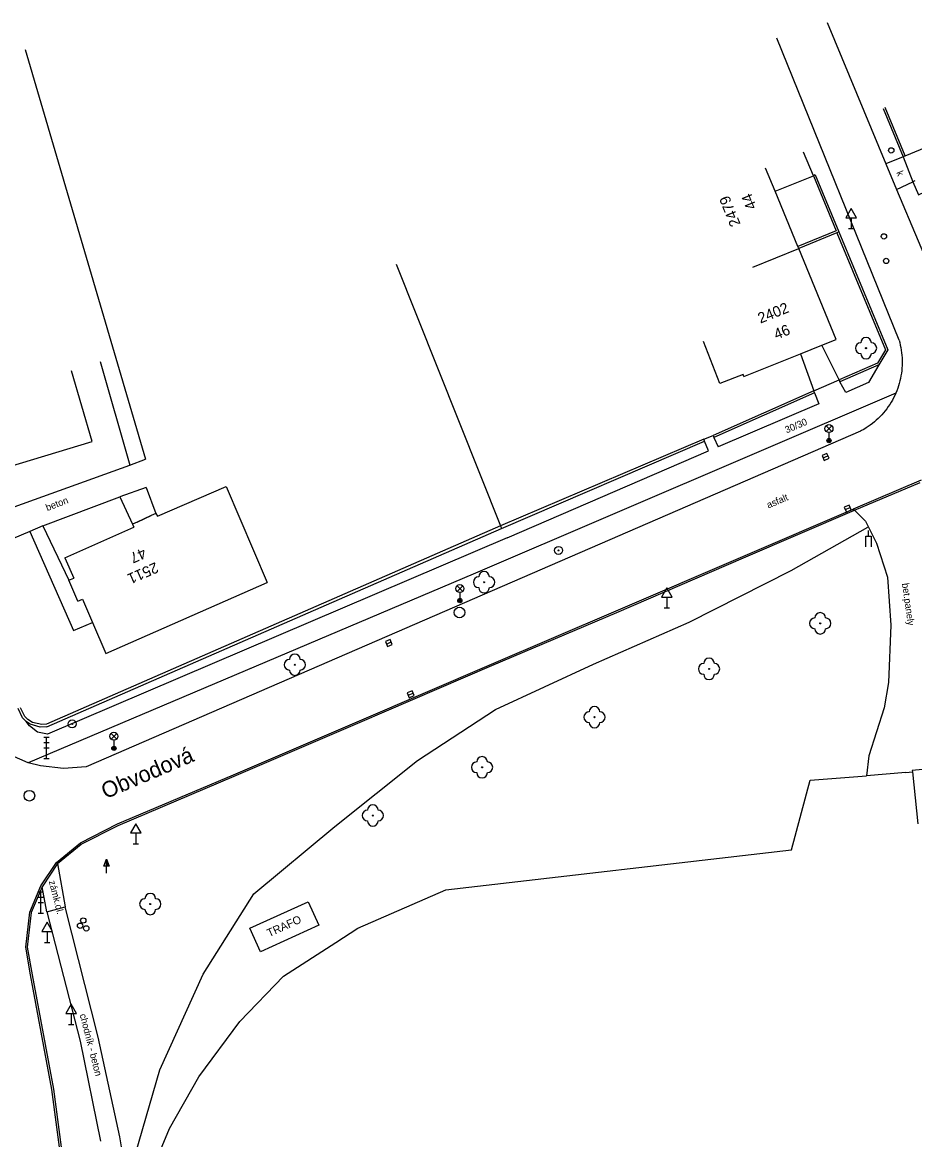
# Model space of a CAD drawing. Extents: x -539694 to -539148, y -1156467 to -1155920.
# Drawn here: x -539640.2 to -539556.6, y -1156122.8 to -1156018.1 of the extents above; entities that cross this region are included whole.
import ezdxf

# ---------------------------------------------------------------- set-up
doc = ezdxf.new("R2010")
doc.units = 0
for name, color, linetype in [('Vrstva 10', 7, 'Continuous'), ('Vrstva 11', 7, 'Continuous'), ('Vrstva 21', 7, 'Continuous'), ('Vrstva 22', 7, 'Continuous'), ('Vrstva 23', 7, 'Continuous'), ('Vrstva 25', 7, 'Continuous'), ('Vrstva 27', 7, 'Continuous'), ('Vrstva 28', 7, 'Continuous'), ('Vrstva 33', 7, 'Continuous'), ('Vrstva 34', 7, 'Continuous'), ('Vrstva 38', 7, 'Continuous'), ('Vrstva 40', 7, 'Continuous'), ('Vrstva 41', 7, 'Continuous'), ('Vrstva 46', 7, 'Continuous'), ('Vrstva 47', 7, 'Continuous'), ('Vrstva 49', 7, 'Continuous'), ('Vrstva 5', 7, 'Continuous'), ('Vrstva 6', 7, 'Continuous'), ('Vrstva 7', 7, 'Continuous'), ('Vrstva 8', 7, 'Continuous')]:
    doc.layers.add(name, color=color, linetype=linetype)

msp = doc.modelspace()

# ---------------------------------------------------------------- linework, layer by layer
at = {"layer": 'Vrstva 10'}
for p, q in [((-539564.79, -1156018.12), (-539559.31, -1156031.39)), ((-539558.07, -1156047.89), (-539569.52, -1156019.6)), ((-539559.31, -1156031.39), (-539558.31, -1156033.77)), ((-539558.31, -1156033.77), (-539553.97, -1156044.1)), ((-539561.68, -1156056.43), (-539634.18, -1156087.87)), ((-539561.575, -1156056.374), (-539561.68, -1156056.43))]:
    msp.add_line(p, q, dxfattribs=at)
for points in [[(-539558.07, -1156047.89), (-539558.006, -1156048.123), (-539557.949, -1156048.359), (-539557.9, -1156048.596), (-539557.859, -1156048.834), (-539557.826, -1156049.074), (-539557.801, -1156049.314), (-539557.784, -1156049.556), (-539557.775, -1156049.798), (-539557.773, -1156050.04), (-539557.78, -1156050.281), (-539557.795, -1156050.523), (-539557.818, -1156050.764), (-539557.849, -1156051.004), (-539557.887, -1156051.243), (-539557.934, -1156051.48), (-539557.988, -1156051.716), (-539558.05, -1156051.95), (-539558.12, -1156052.182), (-539558.197, -1156052.411), (-539558.282, -1156052.637), (-539558.37, -1156052.85), (-539558.475, -1156053.082), (-539558.582, -1156053.299), (-539558.696, -1156053.512), (-539558.817, -1156053.722), (-539558.945, -1156053.927), (-539559.079, -1156054.128), (-539559.221, -1156054.324), (-539559.368, -1156054.516), (-539559.522, -1156054.703), (-539559.682, -1156054.884), (-539559.848, -1156055.061), (-539560.02, -1156055.231), (-539560.197, -1156055.396), (-539560.379, -1156055.555), (-539560.567, -1156055.708), (-539560.76, -1156055.854), (-539560.957, -1156055.994), (-539561.159, -1156056.127), (-539561.365, -1156056.254), (-539561.575, -1156056.374)], [(-539639.62, -1156087.49), (-539641.674, -1156086.595), (-539643.293, -1156085.512), (-539643.537, -1156085.349), (-539645.149, -1156083.793), (-539646.11, -1156082.53)], [(-539634.18, -1156087.87), (-539636.324, -1156088.031), (-539638.461, -1156087.793), (-539639.62, -1156087.49)]]:
    msp.add_lwpolyline(points, dxfattribs=at)
at = {"layer": 'Vrstva 11'}
for p, q in [((-539639.894, -1156020.661), (-539628.648, -1156059.042)), ((-539557.485, -1156030.633), (-539554.04, -1156029.193)), ((-539557.67, -1156030.71), (-539559.31, -1156031.39)), ((-539569.67, -1156033.94), (-539566.094, -1156032.496)), ((-539558.31, -1156033.77), (-539556.77, -1156033.05)), ((-539563.69, -1156051.617), (-539565.31, -1156048.36)), ((-539632.89, -1156049.902), (-539630.1, -1156059.607)), ((-539567.3, -1156049.18), (-539566.061, -1156052.647)), ((-539558.37, -1156052.85), (-539597.95, -1156069.81)), ((-539565.98, -1156052.83), (-539565.59, -1156053.86)), ((-539565.59, -1156053.86), (-539575.018, -1156057.902)), ((-539575.9, -1156058.28), (-539576.28, -1156057.36)), ((-539575.4, -1156057.01), (-539575.018, -1156057.902)), ((-539594.77, -1156066.43), (-539575.9, -1156058.28)), ((-539630.1, -1156059.607), (-539628.648, -1156059.042)), ((-539645.372, -1156065.103), (-539630.1, -1156059.607)), ((-539556, -1156061.02), (-539562.35, -1156063.74)), ((-539562.25, -1156063.84), (-539556.09, -1156061.22)), ((-539638.24, -1156065.3), (-539631.047, -1156062.565)), ((-539628.58, -1156061.711), (-539631.047, -1156062.565)), ((-539631.047, -1156062.565), (-539629.86, -1156065.152)), ((-539628.58, -1156061.711), (-539627.655, -1156064.138)), ((-539572.7, -1156068.17), (-539562.35, -1156063.74)), ((-539562.35, -1156063.74), (-539562.25, -1156063.84)), ((-539572.64, -1156068.3), (-539562.25, -1156063.84)), ((-539639.46, -1156065.83), (-539644.8, -1156068.05)), ((-539638.24, -1156065.3), (-539639.46, -1156065.83)), ((-539639.46, -1156065.83), (-539635.38, -1156075.1)), ((-539638.24, -1156065.3), (-539635.81, -1156070.4)), ((-539594.77, -1156066.43), (-539637.8, -1156084.83)), ((-539584.57, -1156073.27), (-539572.7, -1156068.17)), ((-539584.51, -1156073.4), (-539572.64, -1156068.3)), ((-539597.95, -1156069.81), (-539639.62, -1156087.49)), ((-539559.14, -1156070.1), (-539558.85, -1156074.6)), ((-539596.25, -1156078.26), (-539584.57, -1156073.27)), ((-539596.19, -1156078.39), (-539584.51, -1156073.4)), ((-539635.38, -1156075.1), (-539633.601, -1156074.343)), ((-539558.85, -1156074.6), (-539559.05, -1156079.98)), ((-539608.61, -1156083.55), (-539596.25, -1156078.26)), ((-539608.55, -1156083.68), (-539596.19, -1156078.39)), ((-539620.39, -1156088.61), (-539608.61, -1156083.55)), ((-539620.33, -1156088.74), (-539608.55, -1156083.68)), ((-539631.25, -1156093.23), (-539620.39, -1156088.61)), ((-539631.19, -1156093.36), (-539620.33, -1156088.74)), ((-539636.87, -1156096.93), (-539638.32, -1156099.11)), ((-539636.87, -1156096.93), (-539636.16, -1156101)), ((-539637.89, -1156101.45), (-539638.32, -1156099.11)), ((-539637.89, -1156101.45), (-539636.16, -1156101)), ((-539637.89, -1156101.45), (-539634.77, -1156113.57)), ((-539633.07, -1156113.21), (-539636.16, -1156101)), ((-539637.4, -1156118.11), (-539639.4, -1156107.37)), ((-539639.26, -1156107.35), (-539637.26, -1156118.09)), ((-539634.77, -1156113.57), (-539632.86, -1156122.94)), ((-539631.05, -1156122.54), (-539633.07, -1156113.21)), ((-539636.29, -1156126.52), (-539637.4, -1156118.11)), ((-539637.26, -1156118.09), (-539636.15, -1156126.5)), ((-539629.29, -1156132.71), (-539631.05, -1156122.54))]:
    msp.add_line(p, q, dxfattribs=at)
for points in [[(-539559.95, -1156050.2), (-539560.92, -1156051.88), (-539563.06, -1156052.79), (-539563.61, -1156051.8)], [(-539562.25, -1156063.84), (-539561.21, -1156064.87), (-539560.19, -1156066.92), (-539559.14, -1156070.1)], [(-539559.05, -1156079.98), (-539559.46, -1156082.34), (-539560.9, -1156086.84), (-539561.123, -1156088.724)], [(-539637.8, -1156084.83), (-539638.738, -1156084.617), (-539639.511, -1156084.045), (-539639.8, -1156083.64)], [(-539638.44, -1156099.04), (-539636.98, -1156096.84), (-539634.74, -1156094.99), (-539631.25, -1156093.23)], [(-539636.87, -1156096.93), (-539634.66, -1156095.11), (-539631.19, -1156093.36)], [(-539639.4, -1156107.37), (-539639.85, -1156104.77), (-539639.48, -1156101.49), (-539638.44, -1156099.04)], [(-539638.32, -1156099.11), (-539639.34, -1156101.53), (-539639.71, -1156104.77), (-539639.26, -1156107.35)]]:
    msp.add_lwpolyline(points, dxfattribs=at)
at = {"layer": 'Vrstva 21'}
for centre, radius in [((-539589.96, -1156067.6), 0.375), ((-539589.96, -1156067.6), 0.05), ((-539635.51, -1156083.86), 0.375), ((-539635.51, -1156083.86), 0.05)]:
    msp.add_circle(centre, radius, dxfattribs=at)
at = {"layer": 'Vrstva 22'}
for centre in [(-539561.16, -1156048.65), (-539596.93, -1156070.58), (-539565.45, -1156074.43), (-539614.65, -1156078.31), (-539575.86, -1156078.7), (-539586.59, -1156083.22), (-539597.12, -1156087.92), (-539607.35, -1156092.44), (-539628.19, -1156100.73)]:
    msp.add_circle(centre, 0.05, dxfattribs=at)
for centre, start, end in [((-539561.16, -1156048.15), 0, 180), ((-539561.66, -1156048.65), 90, 270), ((-539560.66, -1156048.65), 270, 90), ((-539561.16, -1156049.15), 180, 0), ((-539596.93, -1156070.08), 0, 180), ((-539597.43, -1156070.58), 90, 270), ((-539596.93, -1156071.08), 180, 0), ((-539596.43, -1156070.58), 270, 90), ((-539565.95, -1156074.43), 90, 270), ((-539565.45, -1156073.93), 0, 180), ((-539564.95, -1156074.43), 270, 90), ((-539565.45, -1156074.93), 180, 0), ((-539614.65, -1156077.81), 0, 180), ((-539615.15, -1156078.31), 90, 270), ((-539614.15, -1156078.31), 270, 90), ((-539576.36, -1156078.7), 90, 270), ((-539575.86, -1156078.2), 0, 180), ((-539575.36, -1156078.7), 270, 90), ((-539614.65, -1156078.81), 180, 0), ((-539575.86, -1156079.2), 180, 0), ((-539586.59, -1156082.72), 0, 180), ((-539587.09, -1156083.22), 90, 270), ((-539586.09, -1156083.22), 270, 90), ((-539586.59, -1156083.72), 180, 0), ((-539597.62, -1156087.92), 90, 270), ((-539597.12, -1156087.42), 0, 180), ((-539596.62, -1156087.92), 270, 90), ((-539597.12, -1156088.42), 180, 0), ((-539607.85, -1156092.44), 90, 270), ((-539607.35, -1156091.94), 0, 180), ((-539606.85, -1156092.44), 270, 90), ((-539607.35, -1156092.94), 180, 0), ((-539628.69, -1156100.73), 90, 270), ((-539628.19, -1156100.23), 0, 180), ((-539627.69, -1156100.73), 270, 90), ((-539628.19, -1156101.23), 180, 0)]:
    msp.add_arc(centre, 0.5, start, end, dxfattribs=at)
at = {"layer": 'Vrstva 23'}
msp.add_lwpolyline([(-539630.21, -1156126.28), (-539627.31, -1156116.28), (-539623.24, -1156107.31), (-539618.5, -1156099.79), (-539610.92, -1156093.46), (-539603.15, -1156087.27), (-539595.85, -1156082.5), (-539586.69, -1156078.25), (-539577.71, -1156074.31), (-539568.17, -1156069.49), (-539560.98, -1156065.43)], dxfattribs=at)
at = {"layer": 'Vrstva 25'}
for p, q in [((-539632.533, -1156097.188), (-539632.28, -1156096.514)), ((-539632.28, -1156097.188), (-539632.533, -1156097.188)), ((-539632.28, -1156097.84), (-539632.28, -1156097.19))]:
    msp.add_line(p, q, dxfattribs=at)
for points in [[(-539632.03, -1156097.19), (-539632.28, -1156097.19), (-539632.28, -1156096.514), (-539632.28, -1156096.514)], [(-539632.088, -1156097.15), (-539632.241, -1156097.15), (-539632.241, -1156096.738)], [(-539632.145, -1156097.111), (-539632.201, -1156097.111), (-539632.201, -1156096.961)]]:
    msp.add_lwpolyline(points, close=True, dxfattribs=at)
at = {"layer": 'Vrstva 27'}
for p, q in [((-539565.184, -1156058.935), (-539564.724, -1156058.737)), ((-539563.1, -1156063.778), (-539562.64, -1156063.582)), ((-539606.081, -1156076.367), (-539605.619, -1156076.173)), ((-539604.04, -1156081.168), (-539603.58, -1156080.972))]:
    msp.add_line(p, q, dxfattribs=at)
for points in [[(-539565.085, -1156059.165), (-539564.625, -1156058.967), (-539564.823, -1156058.507), (-539565.283, -1156058.705)], [(-539563.001, -1156064.008), (-539562.542, -1156063.811), (-539562.739, -1156063.352), (-539563.198, -1156063.549)], [(-539605.984, -1156076.597), (-539605.523, -1156076.404), (-539605.716, -1156075.943), (-539606.177, -1156076.136)], [(-539603.941, -1156081.398), (-539603.482, -1156081.201), (-539603.679, -1156080.742), (-539604.138, -1156080.939)]]:
    msp.add_lwpolyline(points, close=True, dxfattribs=at)
for centre in [(-539599.23, -1156073.42), (-539639.51, -1156090.58)]:
    msp.add_circle(centre, 0.5, dxfattribs=at)
at = {"layer": 'Vrstva 28'}
for centre in [(-539558.8, -1156030.12), (-539559.488, -1156038.175), (-539559.276, -1156040.471), (-539634.47, -1156102.27), (-539634.76, -1156102.76), (-539634.18, -1156103.01)]:
    msp.add_circle(centre, 0.25, dxfattribs=at)
at = {"layer": 'Vrstva 33'}
for p, q in [((-539564.895, -1156056.45), (-539564.365, -1156055.92)), ((-539564.895, -1156055.92), (-539564.365, -1156056.45)), ((-539564.63, -1156056.56), (-539564.63, -1156057.31)), ((-539599.465, -1156071.44), (-539598.935, -1156070.91)), ((-539599.465, -1156070.91), (-539598.935, -1156071.44)), ((-539599.2, -1156071.55), (-539599.2, -1156072.3)), ((-539638.15, -1156085.11), (-539637.65, -1156085.11)), ((-539638.15, -1156085.61), (-539637.65, -1156085.61)), ((-539637.9, -1156087.11), (-539637.9, -1156085.11)), ((-539631.865, -1156085.28), (-539631.335, -1156084.75)), ((-539631.865, -1156084.75), (-539631.335, -1156085.28)), ((-539631.6, -1156085.39), (-539631.6, -1156086.14)), ((-539638.15, -1156086.11), (-539637.65, -1156086.11)), ((-539638.15, -1156087.11), (-539637.65, -1156087.11)), ((-539638.679, -1156099.59), (-539638.181, -1156099.59)), ((-539638.679, -1156100.091), (-539638.181, -1156100.091)), ((-539638.43, -1156101.59), (-539638.43, -1156099.59)), ((-539638.679, -1156100.591), (-539638.181, -1156100.591)), ((-539638.679, -1156101.59), (-539638.181, -1156101.59))]:
    msp.add_line(p, q, dxfattribs=at)
for centre, radius in [((-539564.63, -1156056.185), 0.375), ((-539564.63, -1156057.31), 0.2), ((-539564.63, -1156057.31), 0.145), ((-539564.63, -1156057.31), 0.0876), ((-539599.2, -1156071.175), 0.375), ((-539599.2, -1156072.3), 0.2), ((-539599.2, -1156072.3), 0.145), ((-539599.2, -1156072.3), 0.0876), ((-539631.6, -1156085.015), 0.375), ((-539631.6, -1156086.14), 0.2), ((-539631.6, -1156086.14), 0.145), ((-539631.6, -1156086.14), 0.0876)]:
    msp.add_circle(centre, radius, dxfattribs=at)
at = {"layer": 'Vrstva 34'}
for p, q in [((-539562.56, -1156036.432), (-539562.56, -1156037.45)), ((-539562.81, -1156037.45), (-539562.31, -1156037.45)), ((-539579.82, -1156071.964), (-539579.82, -1156072.98)), ((-539580.07, -1156072.98), (-539579.57, -1156072.98)), ((-539629.55, -1156094.074), (-539629.55, -1156095.09)), ((-539629.8, -1156095.09), (-539629.3, -1156095.09)), ((-539637.86, -1156103.304), (-539637.86, -1156104.32)), ((-539638.11, -1156104.32), (-539637.61, -1156104.32)), ((-539635.61, -1156110.994), (-539635.61, -1156112.01)), ((-539635.86, -1156112.01), (-539635.36, -1156112.01))]:
    msp.add_line(p, q, dxfattribs=at)
for points in [[(-539563.06, -1156036.432), (-539562.06, -1156036.432), (-539562.56, -1156035.566)], [(-539580.32, -1156071.964), (-539579.32, -1156071.964), (-539579.82, -1156071.096)], [(-539630.05, -1156094.074), (-539629.05, -1156094.074), (-539629.55, -1156093.206)], [(-539638.36, -1156103.304), (-539637.36, -1156103.304), (-539637.86, -1156102.436)], [(-539636.11, -1156110.994), (-539635.11, -1156110.994), (-539635.61, -1156110.126)]]:
    msp.add_lwpolyline(points, close=True, dxfattribs=at)
at = {"layer": 'Vrstva 38'}
msp.add_line((-539560.94, -1156066.25), (-539560.94, -1156065.72), dxfattribs=at)
msp.add_lwpolyline([(-539561.19, -1156067.25), (-539561.19, -1156066.25), (-539560.69, -1156066.25), (-539560.69, -1156067.25)], dxfattribs=at)
at = {"layer": 'Vrstva 5'}
for p, q in [((-539569.67, -1156033.94), (-539570.57, -1156031.77)), ((-539567.544, -1156039.112), (-539569.67, -1156033.94)), ((-539571.747, -1156041.055), (-539567.468, -1156039.298)), ((-539567.468, -1156039.298), (-539567.544, -1156039.112)), ((-539563.96, -1156047.84), (-539567.468, -1156039.298)), ((-539574.86, -1156051.96), (-539576.383, -1156048.025)), ((-539565.31, -1156048.36), (-539563.96, -1156047.84)), ((-539567.3, -1156049.18), (-539565.31, -1156048.36)), ((-539572.6, -1156051.3), (-539567.3, -1156049.18)), ((-539633.626, -1156057.4), (-539635.57, -1156050.771)), ((-539572.674, -1156051.114), (-539574.86, -1156051.96)), ((-539572.6, -1156051.3), (-539572.674, -1156051.114)), ((-539642.97, -1156060.22), (-539633.626, -1156057.4)), ((-539627.516, -1156064.404), (-539621.077, -1156061.613)), ((-539621.077, -1156061.613), (-539617.25, -1156070.6)), ((-539629.417, -1156064.948), (-539628.098, -1156064.342)), ((-539627.655, -1156064.138), (-539628.098, -1156064.342)), ((-539627.655, -1156064.138), (-539627.516, -1156064.404)), ((-539636.18, -1156068.28), (-539629.721, -1156065.418)), ((-539629.417, -1156064.948), (-539629.86, -1156065.152)), ((-539629.86, -1156065.152), (-539629.721, -1156065.418)), ((-539636.18, -1156068.28), (-539635.36, -1156070.208)), ((-539635.81, -1156070.4), (-539635.36, -1156070.208)), ((-539634.99, -1156072.35), (-539635.81, -1156070.4)), ((-539632.36, -1156077.26), (-539617.25, -1156070.6)), ((-539634.99, -1156072.35), (-539634.532, -1156072.155)), ((-539634.532, -1156072.155), (-539633.601, -1156074.343)), ((-539633.601, -1156074.343), (-539632.36, -1156077.26)), ((-539550.562, -1156087.594), (-539556.826, -1156088.224)), ((-539556.826, -1156088.224), (-539556.813, -1156088.348)), ((-539556.813, -1156088.348), (-539556.312, -1156093.208)), ((-539618.88, -1156103), (-539613.41, -1156100.51)), ((-539613.41, -1156100.51), (-539612.39, -1156102.72)), ((-539617.86, -1156105.21), (-539618.88, -1156103)), ((-539612.39, -1156102.72), (-539617.86, -1156105.21))]:
    msp.add_line(p, q, dxfattribs=at)
at = {"layer": 'Vrstva 6'}
for p, q in [((-539569.67, -1156033.94), (-539570.57, -1156031.77)), ((-539567.3, -1156049.18), (-539565.31, -1156048.36)), ((-539628.098, -1156064.342), (-539629.415, -1156064.948))]:
    msp.add_line(p, q, dxfattribs=at)
at = {"layer": 'Vrstva 7'}
for p, q in [((-539559.56, -1156026.19), (-539557.67, -1156030.71)), ((-539557.485, -1156030.633), (-539559.375, -1156026.113)), ((-539557.485, -1156030.633), (-539557.67, -1156030.71)), ((-539565.91, -1156032.42), (-539566.094, -1156032.496)), ((-539566.094, -1156032.496), (-539563.961, -1156037.64)), ((-539565.91, -1156032.42), (-539563.7, -1156037.75)), ((-539556.586, -1156032.972), (-539556.77, -1156033.05)), ((-539563.961, -1156037.64), (-539567.544, -1156039.112)), ((-539563.885, -1156037.827), (-539559.343, -1156048.794)), ((-539563.7, -1156037.75), (-539559.12, -1156048.81)), ((-539605.155, -1156040.793), (-539595.383, -1156065.307)), ((-539563.69, -1156051.617), (-539563.61, -1156051.8)), ((-539566.061, -1156052.647), (-539575.481, -1156056.827)), ((-539565.98, -1156052.83), (-539575.4, -1156057.01)), ((-539565.98, -1156052.83), (-539566.061, -1156052.647)), ((-539576.359, -1156057.176), (-539595.383, -1156065.307)), ((-539595.29, -1156065.54), (-539576.28, -1156057.36)), ((-539576.28, -1156057.36), (-539576.359, -1156057.176)), ((-539575.481, -1156056.827), (-539575.4, -1156057.01)), ((-539595.383, -1156065.307), (-539637.92, -1156083.875)), ((-539637.87, -1156084.12), (-539595.29, -1156065.54)), ((-539595.383, -1156065.307), (-539595.29, -1156065.54)), ((-539566.382, -1156089.14), (-539561.123, -1156088.724)), ((-539557.431, -1156088.412), (-539556.813, -1156088.348)), ((-539568.134, -1156095.667), (-539566.382, -1156089.14)), ((-539600.499, -1156099.401), (-539568.134, -1156095.667)), ((-539608.746, -1156102.986), (-539600.499, -1156099.401)), ((-539610.8, -1156104.34), (-539608.746, -1156102.986)), ((-539615.7, -1156107.5), (-539610.8, -1156104.34)), ((-539619.81, -1156111.74), (-539615.7, -1156107.5)), ((-539623.65, -1156116.92), (-539619.81, -1156111.74)), ((-539626.39, -1156121.77), (-539623.65, -1156116.92)), ((-539627.75, -1156125.06), (-539626.39, -1156121.77))]:
    msp.add_line(p, q, dxfattribs=at)
for points in [[(-539556.77, -1156033.05), (-539556.25, -1156034.27), (-539556.066, -1156034.19), (-539552.57, -1156032.71)], [(-539563.7, -1156037.75), (-539563.885, -1156037.827), (-539567.468, -1156039.298)], [(-539559.343, -1156048.794), (-539560.089, -1156050.042), (-539563.69, -1156051.617)], [(-539559.12, -1156048.81), (-539559.95, -1156050.2), (-539563.61, -1156051.8)], [(-539637.87, -1156084.12), (-539638.516, -1156084.16), (-539639.431, -1156083.889), (-539639.8, -1156083.64), (-539640.157, -1156083.27), (-539640.57, -1156082.41)], [(-539637.92, -1156083.875), (-539638.344, -1156083.917), (-539639.221, -1156083.716), (-539639.656, -1156083.44), (-539639.928, -1156083.158), (-539640.33, -1156082.339)]]:
    msp.add_lwpolyline(points, dxfattribs=at)
at = {"layer": 'Vrstva 8'}
for p, q in [((-539566.094, -1156032.496), (-539567.013, -1156030.288)), ((-539557.67, -1156030.71), (-539556.77, -1156033.05)), ((-539566.061, -1156052.647), (-539563.69, -1156051.617)), ((-539576.359, -1156057.176), (-539575.481, -1156056.827)), ((-539557.431, -1156088.412), (-539561.123, -1156088.724))]:
    msp.add_line(p, q, dxfattribs=at)

# ---------------------------------------------------------------- texts
at = {"layer": 'Vrstva 40'}
for s, rotation, p in [('k', 292.79059, (-539558.345, -1156032.192)), ('30/30', 23.20593, (-539568.596, -1156056.641)), ('beton', 20.81834, (-539637.838, -1156063.92)), ('asfalt', 23.16445, (-539570.299, -1156063.68)), ('bet.panely', 278.03574, (-539557.8, -1156070.7)), ('zámk.dl.', 284.436, (-539637.7, -1156098.61)), ('chodník - beton', 284.436, (-539634.81, -1156111.1))]:
    msp.add_text(s, height=0.65, rotation=rotation, dxfattribs=at).set_placement(p)
at = {"layer": 'Vrstva 41'}
msp.add_text('TRAFO', height=0.75, rotation=24.47551, dxfattribs=at).set_placement((-539617.055, -1156103.842))
at = {"layer": 'Vrstva 46'}
for s, rotation, p in [('44', 112.12994, (-539571.379, -1156035.434)), ('46', 21.80141, (-539569.552, -1156047.86)), ('47', 203.78634, (-539628.845, -1156067.321))]:
    msp.add_text(s, height=1, rotation=rotation, dxfattribs=at).set_placement(p)
at = {"layer": 'Vrstva 47'}
for s, rotation, p in [('2479', 112.12994, (-539572.892, -1156037.024)), ('2402', 21.80141, (-539571.053, -1156046.353)), ('2511', 203.78634, (-539627.705, -1156068.677))]:
    msp.add_text(s, height=1, rotation=rotation, dxfattribs=at).set_placement(p)
at = {"layer": 'Vrstva 49'}
msp.add_text('Obvodová', height=1.5, rotation=23.16445, dxfattribs=at).set_placement((-539632.382, -1156090.915))

doc.saveas('drawing.dxf')
